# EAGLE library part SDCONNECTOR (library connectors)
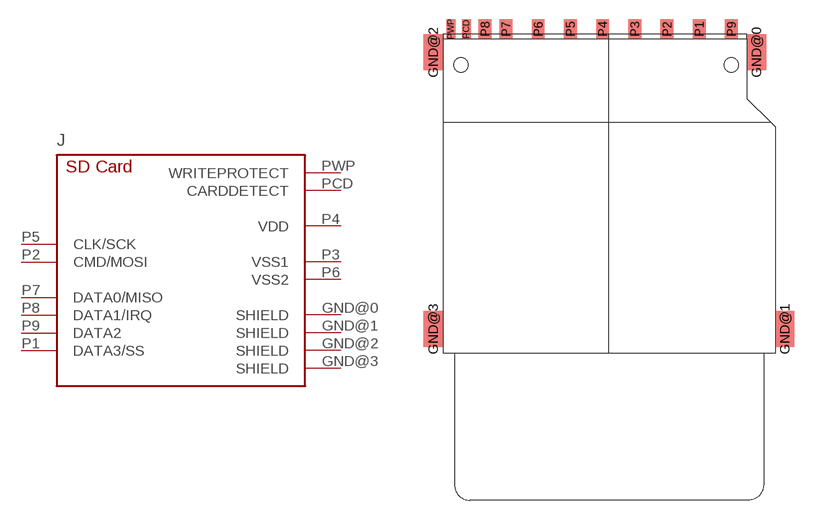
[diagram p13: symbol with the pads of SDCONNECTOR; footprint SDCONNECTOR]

Designator prefix J

## SDCONNECTOR  [SDCONNECTOR]
GND@0  SHIELD  pwr
GND@1  SHIELD  pwr
GND@2  SHIELD  pwr
GND@3  SHIELD  pwr
P1  DATA3/SS
P2  CMD/MOSI  in
P3  VSS1  pwr
P4  VDD  pwr
P5  CLK/SCK  in
P6  VSS2  pwr
P7  DATA0/MISO
P8  DATA1/IRQ
P9  DATA2
PCD  CARDDETECT  pas
PWP  WRITEPROTECT  pas

## Footprint SDCONNECTOR (pad centres in mm)
smd 1.5 x 2.8: GND@0 11.45,5.45; GND@1 13.65,-16.05; GND@2 -13.65,5.45; GND@3 -13.65,-16.05
smd 1 x 1.5: P1 7,7.25; P2 4.5,7.25; P3 2,7.25; P4 -0.5,7.25; P5 -3,7.25; P6 -5.5,7.25; P7 -8,7.25; P8 -9.625,7.25; P9 9.5,7.25
smd 0.7 x 1.5: PCD -11.075,7.25; PWP -12.275,7.25
hole 1.1 at -11.5,4.45
hole 1.1 at 9.5,4.45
